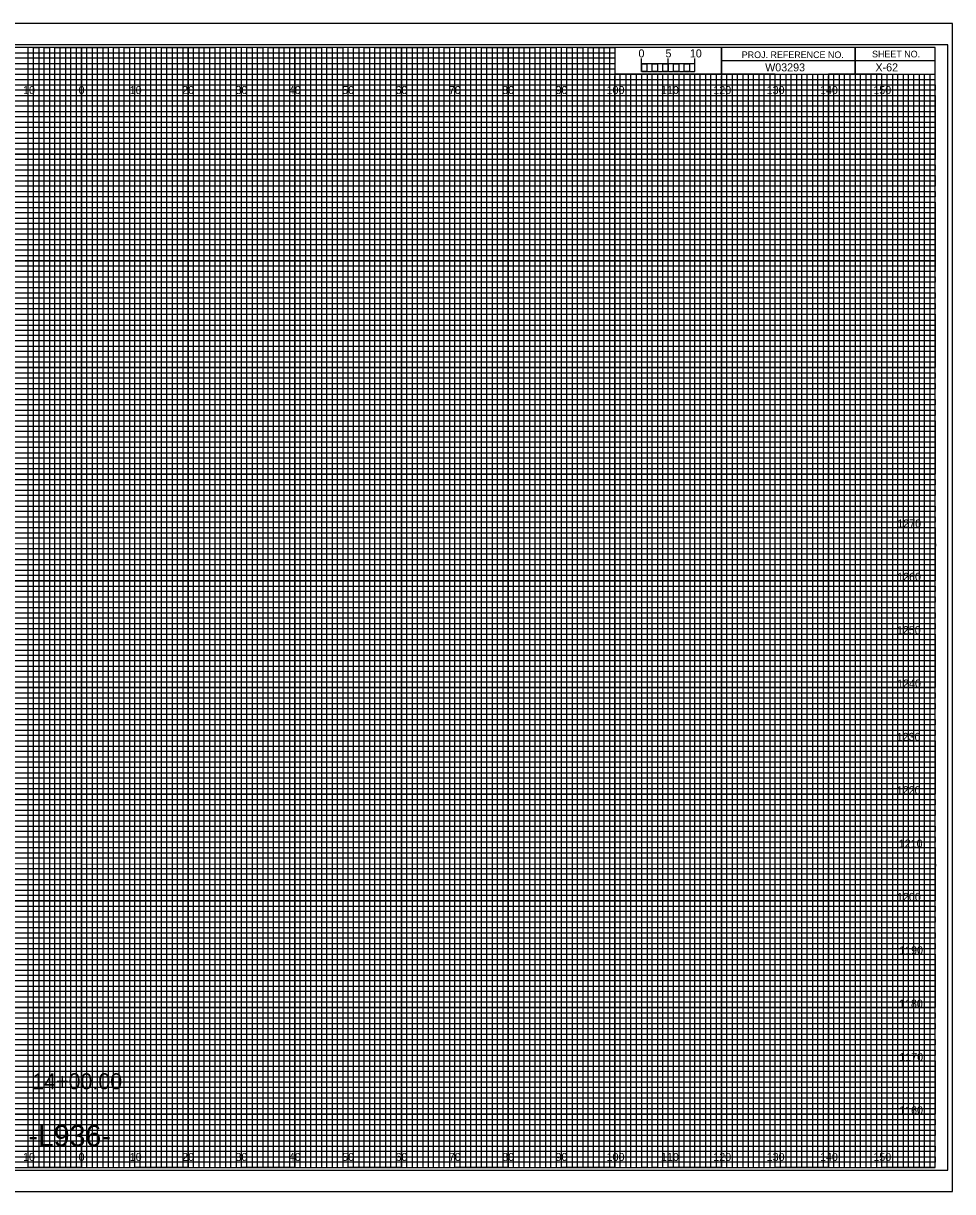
# Model space of a CAD drawing. Extents: x -13 to 323, y 215 to 434.
# Drawn here: x 149.1 to 323.3, y 215.5 to 434.5 of the extents above; entities that cross this region are included whole.
import ezdxf

# ---------------------------------------------------------------- set-up
doc = ezdxf.new("R2010")
doc.units = 0
for name, color, linetype in [('Exist Cross Section Cell', 7, 'Continuous'), ('Exist XS Center Line Elevation Label', 7, 'Continuous'), ('Exist XS Ground Line', 7, 'Continuous'), ('Prop XS Alignment Label', 7, 'Continuous'), ('Prop XS Bar Scale Labels', 7, 'Continuous'), ('Prop XS Finish Grade', 7, 'Continuous'), ('Prop XS Finish Grade Earthwork', 7, 'Continuous'), ('Prop XS Finish Grade Pavement', 7, 'Continuous'), ('Prop XS Project Number', 7, 'Continuous'), ('Prop XS SE Text', 7, 'Continuous'), ('Prop XS Side Slope Text', 7, 'Continuous'), ('Prop XS SS Elevation Text', 7, 'Continuous'), ('Prop XS Subgrade Earthwork', 7, 'Continuous'), ('Prop XSC Text', 7, 'Continuous'), ('Scratch_Level_5', 7, 'Continuous'), ('Typical Curb CELL', 7, 'Continuous'), ('Typical Guardrail CELL', 7, 'Continuous')]:
    doc.layers.add(name, color=color, linetype=linetype)

msp = doc.modelspace()

# ---------------------------------------------------------------- linework, layer by layer
at = {"layer": 'Exist Cross Section Cell'}
for points in [[(145, 220), (155, 220), (155, 430), (165, 430), (165, 220), (175, 220), (175, 430), (185, 430), (185, 220), (195, 220), (195, 430), (205, 430), (205, 220), (215, 220), (215, 430), (225, 430), (225, 220), (235, 220), (235, 430), (245, 430), (245, 220), (255, 220), (255, 430), (259.93, 430), (260, 430), (260, 425), (264.99, 425), (264.99, 220), (275, 220), (275, 425), (285, 425), (285, 220), (295, 220), (295, 425), (305, 425), (305, 220), (315, 220), (315, 425)], [(0, 425), (275, 425)], [(0, 405), (320, 405), (320, 415), (0, 415)], [(0, 385), (320, 385), (320, 395), (0, 395)], [(0, 365), (320, 365), (320, 375), (0, 375)], [(0, 345), (320, 345), (320, 355), (0, 355)], [(0, 325), (320, 325), (320, 335), (0, 335)], [(0, 305), (320, 305), (320, 315), (0, 315)], [(0, 285), (320, 285), (320, 295), (0, 295)], [(0, 265), (320, 265), (320, 275), (0, 275)], [(0, 245), (320, 245), (320, 255), (0, 255)], [(0, 225), (320, 225), (320, 235), (0, 235)]]:
    msp.add_lwpolyline(points, dxfattribs=at)
at = {"layer": 'Exist XS Center Line Elevation Label'}
for p, q in [((150, 430), (140, 430)), ((150, 220), (150, 430)), ((170, 430), (160, 430)), ((160, 430), (160, 220)), ((170, 220), (170, 430)), ((190, 430), (180, 430)), ((180, 430), (180, 220)), ((190, 220), (190, 430)), ((210, 430), (200, 430)), ((200, 430), (200, 220)), ((210, 220), (210, 430)), ((230, 430), (220, 430)), ((220, 430), (220, 220)), ((230, 220), (230, 430)), ((250, 430), (240, 430)), ((240, 430), (240, 220)), ((250, 220), (250, 430)), ((260, 430), (260, 220)), ((270, 220), (270, 425)), ((290, 425), (280, 425)), ((280, 425), (280, 220)), ((290, 220), (290, 425)), ((310, 425), (300, 425)), ((300, 425), (300, 220)), ((310, 220), (310, 425)), ((160, 220), (150, 220)), ((180, 220), (170, 220)), ((200, 220), (190, 220)), ((220, 220), (210, 220)), ((240, 220), (230, 220)), ((260, 220), (250, 220)), ((280, 220), (270, 220)), ((300, 220), (290, 220)), ((320, 220), (310, 220)), ((320, 220), (320, 220))]:
    msp.add_line(p, q, dxfattribs=at)
for points in [[(0, 420), (320, 420), (320, 410), (0, 410)], [(0, 400), (320, 400), (320, 390), (0, 390)], [(0, 380), (320, 380), (320, 370), (0, 370)], [(0, 360), (320, 360), (320, 350), (0, 350)], [(0, 340), (320, 340), (320, 330), (0, 330)], [(0, 320), (320, 320), (320, 310), (0, 310)], [(0, 300), (320, 300), (320, 290), (0, 290)], [(0, 280), (320, 280), (320, 270), (0, 270)], [(0, 260), (320, 260), (320, 250), (0, 250)], [(0, 240), (320, 240), (320, 230), (0, 230)]]:
    msp.add_lwpolyline(points, dxfattribs=at)
at = {"layer": 'Prop XS Finish Grade'}
msp.add_lwpolyline([(-10.8, 219.5), (322.4, 219.5), (322.4, 430.5), (-10.8, 430.5)], close=True, dxfattribs=at)
at = {"layer": 'Prop XS Finish Grade Earthwork'}
for p, q in [((150, 220), (150, 430)), ((160, 220), (160, 430)), ((170, 220), (170, 430)), ((180, 220), (180, 430)), ((190, 220), (190, 430)), ((200, 220), (200, 430)), ((210, 220), (210, 430)), ((220, 220), (220, 430)), ((230, 220), (230, 430)), ((240, 220), (240, 430)), ((250, 220), (250, 430)), ((260, 220), (260, 424.69)), ((270, 220), (270, 424.69)), ((280, 220), (280, 424.69)), ((290, 220), (290, 424.69)), ((300, 220), (300, 424.69)), ((310, 220), (310, 424.69)), ((0, 420), (320, 420)), ((0, 410), (320, 410)), ((0, 400), (320, 400)), ((0, 390), (320, 390)), ((0, 380), (320, 380)), ((0, 370), (320, 370)), ((0, 360), (320, 360)), ((0, 350), (320, 350)), ((0, 340), (320, 340)), ((0, 330), (320, 330)), ((0, 320), (320, 320)), ((0, 310), (320, 310)), ((0, 300), (320, 300)), ((0, 290), (320, 290)), ((0, 280), (320, 280)), ((0, 270), (320, 270)), ((0, 260), (320, 260)), ((0, 250), (320, 250)), ((0, 240), (320, 240)), ((0, 230), (320, 230))]:
    msp.add_line(p, q, dxfattribs=at)
at = {"layer": 'Prop XS Finish Grade Pavement'}
for p, q in [((305, 430), (305, 425)), ((305, 425), (305, 430)), ((280, 427.5), (280, 425)), ((320, 427.49), (280, 427.49)), ((280, 425), (320, 425))]:
    msp.add_line(p, q, dxfattribs=at)
for points in [[(320, 430), (0, 430), (0, 220), (320, 220)], [(280, 430), (260, 430), (260, 425.03), (280, 425.03)], [(320, 430), (280, 430), (280, 425), (320, 425)]]:
    msp.add_lwpolyline(points, close=True, dxfattribs=at)
at = {"layer": 'Prop XS Subgrade Earthwork'}
msp.add_lwpolyline([(-13.4, 215.5), (323.3, 215.5), (323.3, 434.5), (-13.4, 434.5)], close=True, dxfattribs=at)
at = {"layer": 'Prop XSC Text'}
for p, q in [((323.3, 434.5), (-13.4, 434.5)), ((-13.4, 215.5), (323.3, 215.5))]:
    msp.add_line(p, q, dxfattribs=at)
at = {"layer": 'Scratch_Level_5'}
for p, q in [((0, 429), (260, 429)), ((260, 427.98), (0, 427.98)), ((260, 429), (260, 427.98)), ((0, 427), (260, 427)), ((260, 425.89), (0, 425.89)), ((260, 427), (260, 425.89)), ((0, 424), (320, 424))]:
    msp.add_line(p, q, dxfattribs=at)
for points in [[(0, 423), (270, 423), (320, 423), (320, 422), (0, 422)], [(0, 421), (320, 421), (320, 419), (0, 419)], [(0, 418), (320, 418), (320, 417), (0, 416.98)], [(0, 416), (320, 416), (320, 414), (0, 414)], [(0, 413), (320, 413), (320, 412), (0, 412)], [(0, 411), (320, 411), (320, 409), (0, 409)], [(0, 408), (320, 408), (320, 407), (0, 407)], [(0, 406), (320, 406), (320, 404), (0, 404)], [(0, 403), (320, 403), (320, 402), (0, 402)], [(0, 401), (320, 401), (320, 399), (0, 399)], [(0, 398), (320, 398), (320, 397), (0, 397)], [(0, 396), (320, 396), (320, 393.95), (320, 393), (320, 392), (0, 392)], [(0, 394), (320, 394), (320, 393), (0, 393)], [(0, 391), (320, 391), (320, 389), (0, 389.03)], [(0, 389.03), (320, 389), (320, 388), (0, 388)], [(0, 387), (320, 387), (320, 386), (0, 386)], [(0, 384), (320, 384), (320, 383), (0, 383)], [(0, 382), (320, 382), (320, 381), (0, 381)], [(-0.07, 378.89), (320, 378.89), (320, 377.88), (-0.07, 377.88)], [(0, 377), (320, 377), (320, 376), (0, 376)], [(0, 374), (320, 374), (320, 373), (0, 373)], [(0, 372), (320, 372), (320, 371), (0, 371)], [(0, 369), (320, 369), (320, 368), (0, 368)], [(0, 367), (320, 367), (320, 366), (0, 366)], [(0, 364), (320, 364), (320, 363), (0, 363)], [(0, 362), (320, 362), (320, 361), (0, 361)], [(0, 359), (320, 359), (319.99, 357.98), (0, 358)], [(0, 357), (320, 357), (320, 356), (0, 356)], [(0, 354), (320, 354), (320, 353), (0, 353)], [(0, 352), (320, 352), (320, 351), (0, 351)], [(0, 349), (320, 349), (320, 348), (0, 348)], [(0, 347), (320, 347), (320, 346), (0, 346)], [(0, 344), (320, 344), (320, 343), (0, 343)], [(0, 342), (320, 342), (320, 341), (0, 341)], [(0, 339), (320, 339), (320, 338), (0, 338)], [(0, 336.99), (320.07, 336.91), (320, 336), (0, 336)], [(0, 334), (320, 334), (320, 333), (0, 333)], [(0, 332), (320, 332), (320, 331), (0, 331)], [(0, 329), (320, 329), (320, 328), (0, 328)], [(0, 327), (320, 327), (320, 326), (0, 326)], [(0, 324), (320, 324), (320, 323), (0, 323)], [(0, 322), (320, 322), (320, 321), (0, 321)], [(0, 319), (320, 319), (320, 318), (0, 318)], [(0, 317), (320, 317), (320, 316), (0, 316)], [(0, 314), (320, 314), (320, 313), (0, 313)], [(0, 312), (320, 312), (320, 311), (0, 311)], [(0, 309), (320, 309), (320, 308), (0, 308)], [(0, 307), (320, 307), (320, 306), (0, 306)], [(0, 304), (320, 304), (320, 303), (0, 303)], [(0, 302), (320, 302), (320, 301), (0, 301)], [(0, 299), (320, 299), (319.99, 297.98), (0, 298)], [(0, 297), (320, 297), (320, 296), (0, 296)], [(0, 294), (320, 294), (320, 293), (0, 293)], [(0, 292), (320, 292), (320, 291), (0, 291)], [(0, 289), (320, 289), (320, 288), (0, 288)], [(0, 287), (320, 287), (320, 286), (0, 286)], [(0, 284), (320, 284), (320, 283), (0, 283)], [(0, 282), (320, 282), (320, 281), (0, 281)], [(0, 279), (320, 279), (320, 278), (0, 278)], [(0, 276.99), (320.07, 276.91), (320, 276), (0, 276)], [(0, 274), (320, 274), (320, 273), (0, 273)], [(0, 272), (320, 272), (320, 271), (0, 271)], [(0, 269), (320, 269), (320, 268), (0, 268)], [(0, 267), (320, 267), (320, 266), (0, 266)], [(0, 264), (320, 264), (320, 263), (0, 263)], [(0, 262), (320, 262), (320, 261), (0, 261)], [(0, 259), (320, 259), (320, 258), (0, 258)], [(0, 257), (320, 257), (320, 256), (0, 256)], [(0, 254), (320, 254), (320, 253), (0, 253)], [(0, 252), (320, 252), (320, 251), (0, 251)], [(0, 249), (320, 249), (320, 248), (0, 248)], [(0, 247), (320, 247), (320, 246), (0, 246)], [(0, 244), (320, 244), (320, 243), (0, 243)], [(0, 242), (320, 242), (320, 241), (0, 241)], [(0, 239), (320, 239), (320, 238), (0, 238)], [(0, 237), (320, 237), (320, 236), (0, 236)], [(0, 234), (320, 234), (320, 233), (0, 233)], [(0, 232), (320, 232), (320, 231), (0, 231)], [(0, 229), (320, 229), (320, 228), (0, 228)], [(0, 227), (320, 227), (320, 226), (0, 226)], [(0, 224), (320, 224), (320, 223), (0, 223)], [(0, 222), (320, 222), (320, 221), (0, 221)]]:
    msp.add_lwpolyline(points, dxfattribs=at)
at = {"layer": 'Typical Curb CELL'}
for p, q in [((267, 425), (266.01, 425)), ((266.01, 425), (266.01, 220)), ((267, 220), (267, 425)), ((269, 425), (268, 425)), ((268, 425), (268, 220)), ((269, 220), (269, 425)), ((266.01, 220), (265, 220)), ((268, 220), (267, 220))]:
    msp.add_line(p, q, dxfattribs=at)
for points in [[(150, 220), (151, 220), (151, 430), (152, 430), (152, 220)], [(152, 220), (153, 220), (153, 430), (154, 430), (154, 220)], [(155, 220), (156, 220), (156, 430), (157, 430), (157, 220)], [(157, 220), (158, 220), (158, 430), (159, 430), (159, 220)], [(160, 220), (161, 220), (161, 430), (162, 430), (162, 220)], [(162, 220), (163, 220), (163, 430), (164, 430), (164, 220)], [(165, 220), (166, 220), (166, 430), (167, 430), (167, 220)], [(167, 220), (168, 220), (168, 430), (169, 430), (169, 220)], [(170, 220), (171, 220), (171, 430), (172, 430), (172, 220)], [(172, 220), (173, 220), (173, 430), (174, 430), (174, 220)], [(175, 220), (176, 220), (176, 430), (177, 430), (177, 220)], [(177, 220), (178, 220), (178, 430), (179, 430), (179, 220)], [(180, 220), (181, 220), (181, 430), (182, 430), (182, 220)], [(182, 220), (183, 220), (183, 430), (184, 430), (184, 220)], [(185, 220), (186, 220), (186, 430), (187, 430), (187, 220)], [(187, 220), (188, 220), (188, 430), (189, 430), (189, 220)], [(190, 220), (191, 220), (191, 430), (192, 430), (192, 220)], [(192, 220), (193, 220), (193, 430), (194, 430), (194, 220)], [(195, 220), (196, 220), (196, 430), (197, 430), (197, 220)], [(197, 220), (198, 220), (198, 430), (199, 430), (199, 220)], [(200, 220), (201, 220), (201, 430), (202, 430), (202, 220)], [(202, 220), (203, 220), (203, 430), (204, 430), (204, 220)], [(205, 220), (206, 220), (206, 430), (207, 430), (207, 220)], [(207, 220), (208, 220), (208, 430), (209, 430), (209, 220)], [(210, 220), (211, 220), (211, 430), (212, 430), (212, 220)], [(212, 220), (213, 220), (213, 430), (214, 430), (214, 220)], [(215, 220), (216, 220), (216, 430), (217, 430), (217, 220)], [(217, 220), (218, 220), (218, 430), (219, 430), (219, 220)], [(220, 220), (221, 220), (221, 430), (222, 430), (222, 220)], [(222, 220), (223, 220), (223, 430), (224, 430), (224, 220)], [(225, 220), (226, 220), (226, 430), (227, 430), (227, 220)], [(227, 220), (228, 220), (228, 430), (229, 430), (229, 220)], [(230, 220), (231, 220), (231, 430), (232, 430), (232, 220)], [(232, 220), (233, 220), (233, 430), (234, 430), (234, 220)], [(235, 220), (236, 220), (236, 430), (237, 430), (237, 220)], [(237, 220), (238, 220), (238, 430), (239, 430), (239, 220)], [(240, 220), (241, 220), (241, 430), (242, 430), (242, 220)], [(242, 220), (243, 220), (243, 430), (244, 430), (244, 220)], [(245, 220), (246, 220), (246, 430), (247, 430), (247, 220)], [(247, 220), (248, 220), (248, 430), (249, 430), (249, 220)], [(250, 220), (251, 220), (251, 430), (252, 430), (252, 220)], [(252, 220), (253, 220), (253, 430), (254, 430), (254, 220)], [(255, 220), (256, 220), (256, 430), (257, 430), (257, 220)], [(257, 220), (258, 220), (258, 430), (259, 430), (259, 220)], [(260, 220), (261, 220), (261, 425), (262.02, 425), (262.02, 220)], [(262, 220), (263, 220), (263, 425), (263.99, 425), (263.99, 220)], [(270, 220), (270.98, 220), (270.98, 425), (272, 425), (272, 220)], [(272, 220), (273, 220), (273, 425), (274.05, 425), (274.05, 220)], [(275, 220), (276, 220), (276, 425), (277, 425), (277, 220)], [(277, 220), (278, 220), (278, 425), (279, 425), (279, 220)], [(280, 220), (281, 220), (281, 425), (282, 425), (282, 220)], [(282, 220), (283, 220), (283, 425), (284, 425), (284, 220)], [(285, 220), (286, 220), (286, 425), (287, 425), (287, 220)], [(287, 220), (288, 220), (288, 425), (289, 425), (289, 220)], [(290, 220), (291, 220), (291, 425), (292, 425), (292, 220)], [(292, 220), (293, 220), (293, 425), (294, 425), (294, 220)], [(295, 220), (296, 220), (296, 425), (297, 425), (297, 220)], [(297, 220), (298, 220), (298, 425), (299, 425), (299, 220)], [(300, 220), (301, 220), (301, 425), (302, 425), (302, 220)], [(302, 220), (303, 220), (303, 425), (304, 425), (304, 220)], [(305, 220), (306, 220), (306, 425), (307, 425), (307, 220)], [(307, 220), (308, 220), (308, 425), (309, 425), (309, 220)], [(310, 220), (311, 220), (311, 425), (312, 425), (312, 220)], [(312, 220), (313, 220), (313, 425), (314, 425), (314, 220)], [(315, 220), (316, 220), (316, 425), (317, 425), (317, 220)], [(317, 220), (318, 220), (318, 425), (319, 425), (319, 220)]]:
    msp.add_lwpolyline(points, dxfattribs=at)
at = {"layer": 'Typical Guardrail CELL'}
for p, q in [((265, 425.49), (265, 427.9)), ((265, 426.9), (265, 427.9)), ((270, 425.49), (270, 427.9)), ((275, 425.49), (275, 427.9)), ((275, 426.9), (275, 427.9))]:
    msp.add_line(p, q, dxfattribs=at)
for points in [[(275, 426.9), (265, 426.9), (265, 425.49), (275, 425.49)], [(265, 426.9), (266, 426.9), (266, 425.49), (265, 425.49)], [(267, 426.9), (268, 426.9), (268, 425.49), (267, 425.49)], [(269, 426.9), (270, 426.9), (270, 425.49), (269, 425.49)], [(271, 426.9), (272, 426.9), (272, 425.49), (271, 425.49)], [(273, 426.9), (274, 426.9), (274, 425.49), (273, 425.49)]]:
    msp.add_lwpolyline(points, close=True, dxfattribs=at)

# ---------------------------------------------------------------- texts
at = {"layer": 'Exist XS Ground Line'}
for s, p in [('10', (149.04, 421.25)), ('0', (159.45, 421.25)), ('0', (159.45, 421.25)), ('10', (169.04, 421.25)), ('20', (178.86, 421.25)), ('30', (188.86, 421.25)), ('40', (198.86, 421.25)), ('50', (208.86, 421.25)), ('60', (218.86, 421.25)), ('70', (228.86, 421.25)), ('80', (238.86, 421.25)), ('90', (248.86, 421.25)), ('100', (258.44, 421.25)), ('110', (268.62, 421.25)), ('120', (278.44, 421.25)), ('130', (288.44, 421.25)), ('140', (298.44, 421.25)), ('150', (308.44, 421.25)), ('10', (149.04, 221.25)), ('0', (159.45, 221.25)), ('0', (159.45, 221.25)), ('10', (169.04, 221.25)), ('20', (178.86, 221.25)), ('30', (188.86, 221.25)), ('40', (198.86, 221.25)), ('50', (208.86, 221.25)), ('60', (218.86, 221.25)), ('70', (228.86, 221.25)), ('80', (238.86, 221.25)), ('90', (248.86, 221.25)), ('100', (258.44, 221.25)), ('110', (268.62, 221.25)), ('120', (278.44, 221.25)), ('130', (288.44, 221.25)), ('140', (298.44, 221.25)), ('150', (308.44, 221.25))]:
    msp.add_text(s, height=1.5, dxfattribs=at).set_placement(p)
at = {"layer": 'Prop XS Alignment Label'}
msp.add_text('-L936-', height=4, dxfattribs=at).set_placement((150.03, 224))
at = {"layer": 'Prop XS Bar Scale Labels'}
for s, p in [('5', (269.47, 428.12)), ('10', (274.04, 428.12))]:
    msp.add_text(s, height=1.5, dxfattribs=at).set_placement(p)
at = {"layer": 'Prop XS Finish Grade Pavement'}
for s, p in [('PROJ. REFERENCE NO.', (283.77, 427.99)), ('SHEET NO.', (308.19, 428.12))]:
    msp.add_text(s, height=1.25, dxfattribs=at).set_placement(p)
at = {"layer": 'Prop XS Project Number'}
msp.add_text(' W03293', height=1.5, dxfattribs=at).set_placement((287.6, 425.5))
at = {"layer": 'Prop XS SE Text'}
msp.add_text('X-62', height=1.5, dxfattribs=at).set_placement((308.83, 425.5))
at = {"layer": 'Prop XS Side Slope Text'}
for s, p in [('1270', (312.93, 340)), ('1260', (312.9, 330)), ('1250', (312.85, 320)), ('1240', (312.9, 310)), ('1230', (312.82, 300)), ('1220', (312.83, 290)), ('1210', (313.2, 280)), ('1200', (312.87, 270)), ('1190', (313.28, 260)), ('1180', (313.25, 250)), ('1170', (313.31, 240)), ('1160', (313.28, 230))]:
    msp.add_text(s, height=1.5, dxfattribs=at).set_placement(p)
at = {"layer": 'Prop XS SS Elevation Text'}
msp.add_text('14+00.00', height=3, dxfattribs=at).set_placement((150.77, 234.69))
at = {"layer": 'Typical Guardrail CELL'}
msp.add_text('0', height=1.5, dxfattribs=at).set_placement((264.41, 428.12))

doc.saveas('drawing.dxf')
